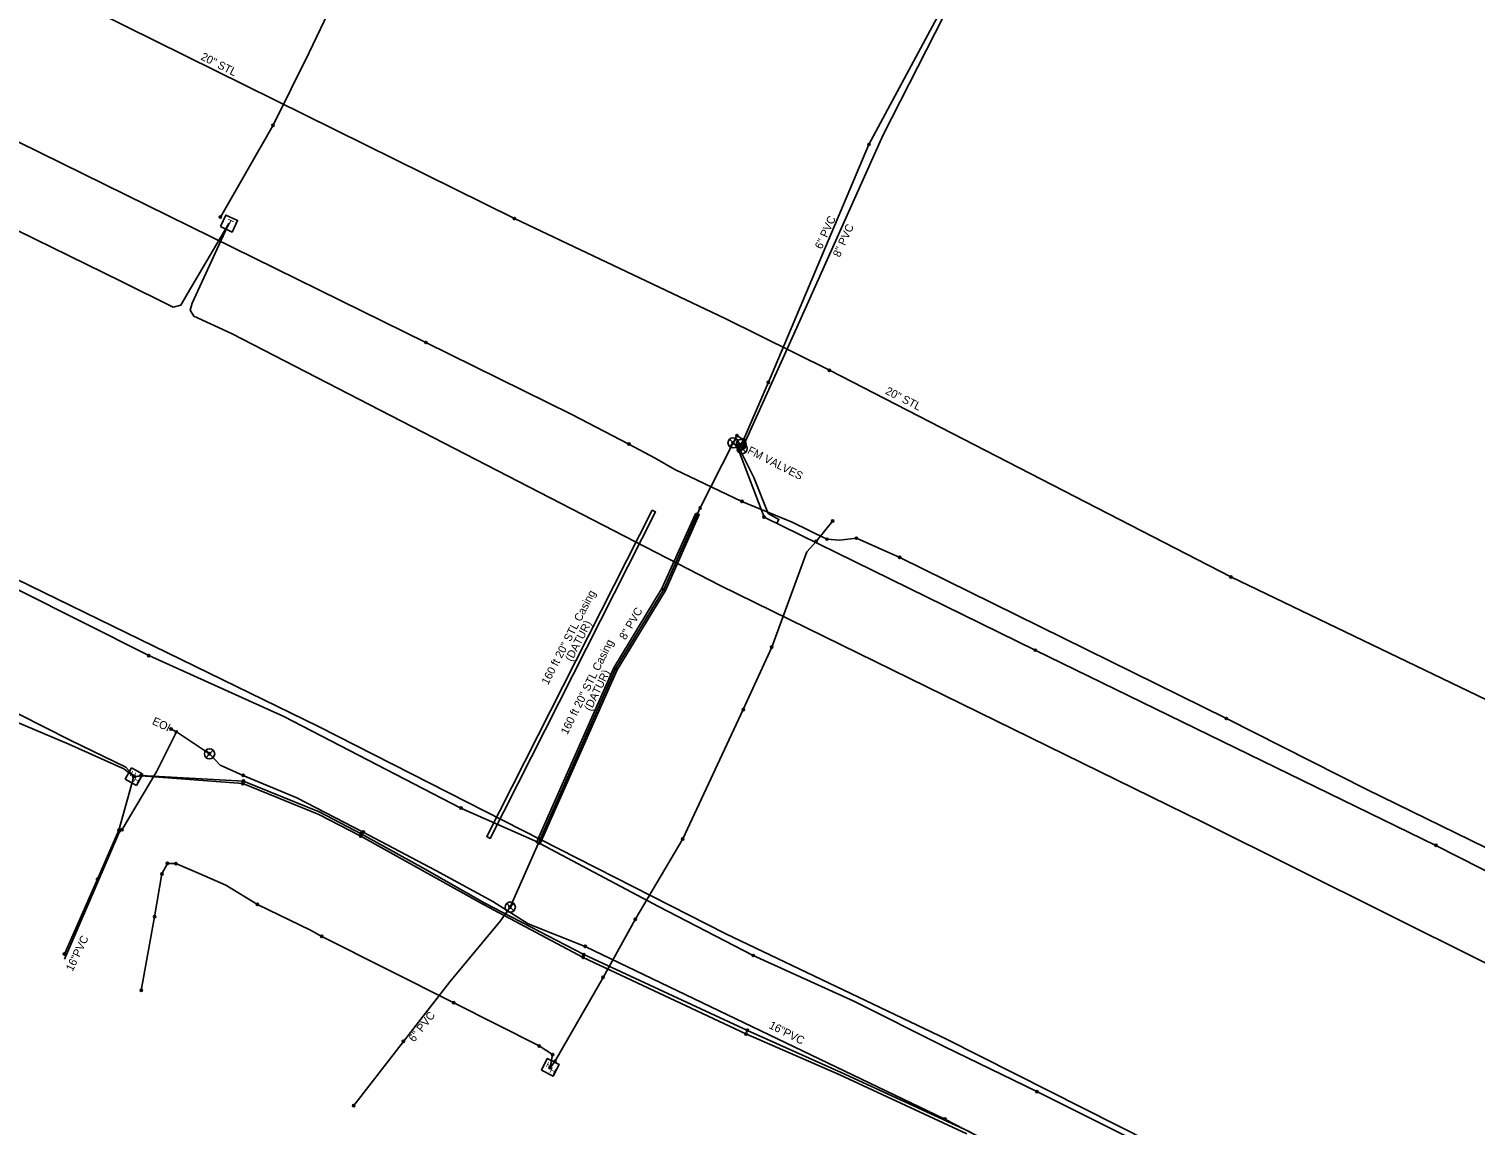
# Model space of a CAD drawing. Extents: x 2244485 to 2250986, y 199568 to 203007.
# Drawn here: x 2245302 to 2245934, y 202136 to 202615 of the extents above; entities that cross this region are included whole.
import ezdxf

# ---------------------------------------------------------------- set-up
doc = ezdxf.new("R2010")
doc.units = 0
for name, color, linetype in [('Default', 7, 'Continuous'), ('Exist Structure Minor Storm Sewer Line Text', 7, 'Continuous'), ('Exist Utilities Gas UG Line SUE LOS B', 7, 'Continuous'), ('Exist Utilities Gas UG Line SUE LOS B Text', 7, 'Continuous'), ('Exist Utilities Power UG Cable SUE LOS B', 7, 'Continuous'), ('Exist Utilities Sanitary Sewer Forced Main SUE LOS B', 7, 'Continuous'), ('Exist Utilities Sanitary Sewer Forced Main SUE LOS B Text', 7, 'Continuous'), ('Exist Utilities Sanitary Sewer Forced Main SUE LOS C', 7, 'Continuous'), ('Exist Utilities Telephone Hand Hole CELL', 7, 'Continuous'), ('Exist Utilities Telephone Pedestal CELL', 7, 'Continuous'), ('Exist Utilities Telephone UG Cable SUE LOS C', 7, 'Continuous'), ('Exist Utilities Telephone UG FO SUE LOS B', 7, 'Continuous'), ('Exist Utilities Telephone UG FO SUE LOS C', 7, 'Continuous'), ('Exist Utilities TV Hand Hole CELL', 7, 'Continuous'), ('Exist Utilities TV UG FO Cable SUE LOS B', 7, 'Continuous'), ('Exist Utilities Water UG Line SUE LOS B', 7, 'Continuous'), ('Exist Utilities Water UG Line SUE LOS B Text', 7, 'Continuous'), ('Exist Utilities Water Valve CELL', 7, 'Continuous')]:
    doc.layers.add(name, color=color, linetype=linetype)

# ---------------------------------------------------------------- blocks, each defined once
blk = doc.blocks.new('SurveyPointCell')
at = {"layer": 'Default'}
for p, q in [((-0.5, 0), (0.5, 0)), ((0, -0.5), (0, 0.5))]:
    blk.add_line(p, q, dxfattribs=at)
blk.add_circle((0, 0), 0.5, dxfattribs=at)

msp = doc.modelspace()

# ---------------------------------------------------------------- linework, layer by layer
at = {"layer": 'Exist Structure Minor Storm Sewer Line Text'}
for points in [[(2245574.64, 202404.29), (2245576.13, 202403.54), (2245503.77, 202260.84), (2245502.28, 202261.59)], [(2245593.72, 202403.05), (2245595.24, 202402.37), (2245580.4, 202369.24), (2245559.29, 202334.56), (2245525.57, 202258.34), (2245524.04, 202259.02), (2245557.81, 202335.34), (2245578.92, 202370.01)]]:
    msp.add_lwpolyline(points, close=True, dxfattribs=at)
at = {"layer": 'Exist Utilities Gas UG Line SUE LOS B'}
msp.add_lwpolyline([(2244658.96, 202958.49), (2244721.96, 202928.3), (2244863.47, 202856.19), (2244912.51, 202831.57), (2245070.07, 202752.33), (2245256.14, 202659.91), (2245331.4, 202622.29), (2245514.38, 202531.76), (2245606.53, 202488.05), (2245652.12, 202465.42), (2245827.69, 202375.08), (2246001.01, 202291.84), (2246162.3, 202211.17), (2246329.12, 202125.74), (2246513.99, 202036.93), (2246642.7, 201974.75), (2246734.96, 201930.33), (2246858.92, 201868.26), (2246999.42, 201799.12), (2247177.53, 201710.71), (2247331.7, 201633.3), (2247466.92, 201567.22), (2247602.4, 201501.88), (2247749.1, 201426.01)], dxfattribs=at)
at = {"layer": 'Exist Utilities Power UG Cable SUE LOS B'}
msp.add_lwpolyline([(2245385.83, 202532.39), (2245408.84, 202572.53), (2245424.65, 202604.36), (2245434.48, 202624.66), (2245451.18, 202657.41), (2245437.28, 202665.96)], dxfattribs=at)
at = {"layer": 'Exist Utilities Sanitary Sewer Forced Main SUE LOS B'}
for points in [[(2245613.42, 202432.81), (2245614.64, 202435.08), (2245625.46, 202460.2), (2245669.41, 202564.11), (2245700.29, 202621.51)], [(2245512.48, 202230.83), (2245558.55, 202334.95), (2245579.66, 202369.62), (2245595.61, 202405.24), (2245610, 202433.72), (2245611.68, 202436.87), (2245614.64, 202435.08)], [(2245613.42, 202432.81), (2245612.33, 202430.62), (2245623.54, 202401.29), (2245742.14, 202343.1), (2245917.37, 202257.79), (2246026.41, 202202.34), (2246210.46, 202111.93), (2246345.24, 202046.28), (2246501.59, 201967.74), (2246585.87, 201926.12), (2246766.44, 201836.2), (2246874.3, 201784.12), (2246993.56, 201724.08), (2247186.6, 201626.85), (2247291.7, 201574.36), (2247419.93, 201509.91), (2247528.38, 201455.85), (2247631.36, 201405.97), (2247735.41, 201350.67), (2247801.59, 201317.51)], [(2245444.17, 202144.04), (2245465.88, 202172.11), (2245486.13, 202198.15), (2245508.27, 202224.8), (2245512.48, 202230.83)]]:
    msp.add_lwpolyline(points, dxfattribs=at)
at = {"layer": 'Exist Utilities Sanitary Sewer Forced Main SUE LOS C'}
msp.add_lwpolyline([(2245629.15, 202398.66), (2245630.09, 202400.26), (2245625.31, 202402.84), (2245619.07, 202418.57), (2245613.43, 202429.99), (2245613.98, 202431.19), (2245637.91, 202484.15), (2245675.61, 202568.28), (2245702.23, 202620.32), (2245700.29, 202621.51)], dxfattribs=at)
at = {"layer": 'Exist Utilities Telephone Hand Hole CELL'}
for p, q in [((2245346.95, 202291.69), (2245344.18, 202286.68)), ((2245351.96, 202288.92), (2245346.95, 202291.69)), ((2245349.19, 202283.91), (2245351.96, 202288.92)), ((2245344.18, 202286.68), (2245349.19, 202283.91)), ((2245348.07, 202287.8), (2245348.07, 202287.8))]:
    msp.add_line(p, q, dxfattribs=at)
at = {"layer": 'Exist Utilities Telephone Pedestal CELL'}
msp.add_line((2245389.55, 202529.63), (2245389.55, 202529.63), dxfattribs=at)
msp.add_lwpolyline([(2245385.88, 202528.23), (2245390.95, 202525.86), (2245393.32, 202530.92), (2245388.26, 202533.3), (2245385.88, 202528.23)], dxfattribs=at)
at = {"layer": 'Exist Utilities Telephone UG Cable SUE LOS C'}
msp.add_lwpolyline([(2245130.24, 202608.24), (2245342.53, 202504.23), (2245365.2, 202493.05), (2245368.49, 202493.82), (2245371.26, 202498.68), (2245389.55, 202529.63), (2245373.43, 202494.83), (2245372.62, 202491.73), (2245374.18, 202489.1), (2245390.76, 202481.45), (2245604.3, 202371.42), (2245815.4, 202267.89), (2246098.91, 202126.77), (2246431.3, 201961.17), (2246435.26, 201960.69), (2246439.92, 201963.48), (2246448.75, 201975.62), (2246463.67, 201997.05), (2246446.22, 201961.62), (2246445.59, 201956.98), (2246446.26, 201954.54), (2246473.42, 201940.75), (2246700.68, 201828.04)], dxfattribs=at)
at = {"layer": 'Exist Utilities Telephone UG FO SUE LOS B'}
for points in [[(2244534.64, 202709.84), (2244609.27, 202669.97), (2244785.74, 202581.01), (2244840.19, 202553.14), (2244956.88, 202500.62), (2244986.55, 202486.03), (2245010.04, 202472.71), (2245040, 202457.4), (2245084.78, 202430.15), (2245170.23, 202380.19), (2245207.23, 202360.21), (2245246.97, 202340.05), (2245286.61, 202320.72), (2245320.18, 202303.77), (2245344.49, 202291.92), (2245347.99, 202287.98)], [(2245260.01, 202583.68), (2245475.72, 202477.57), (2245539.46, 202446.04), (2245564.49, 202433.2), (2245575.96, 202427.09), (2245584.49, 202422.12), (2245613.86, 202408.13), (2245635.9, 202399.1), (2245651.03, 202391.62), (2245656.6, 202391.2), (2245663.92, 202392.06), (2245682.86, 202383.66), (2245825.7, 202313.24), (2245887.18, 202282.16), (2245945.52, 202253.66), (2246007.29, 202222.98), (2246067.19, 202192.91), (2246123.94, 202164.93), (2246186.06, 202132.91)], [(2244991.72, 202447.43), (2244997.62, 202457.3), (2244999.68, 202459.77), (2245003.89, 202458.01), (2245037.21, 202441.81), (2245081.53, 202417.4), (2245166.02, 202372.45), (2245244.84, 202333.87), (2245285.27, 202316.42), (2245319.61, 202302.06), (2245343.58, 202291.26), (2245348.02, 202287.91)], [(2245297.18, 202369.62), (2245354.5, 202340.75), (2245413.57, 202314.06), (2245491.04, 202274.06), (2245523.39, 202259.78), (2245577.45, 202231.04), (2245618.81, 202209.65), (2245662.83, 202189.65), (2245702.29, 202169.93), (2245742.87, 202150.13), (2245837.39, 202103.05), (2245884.95, 202080.1), (2245941.39, 202052.03), (2246102.15, 201972.13), (2246160.8, 201943.07), (2246225.68, 201910.57), (2246354.46, 201846.2), (2246394.94, 201822.07), (2246546.85, 201748.25)], [(2245317.61, 202210.29), (2245332.09, 202242.94), (2245341.42, 202264.38), (2245347.93, 202287.91)], [(2245348.07, 202287.8), (2245351.12, 202288.29), (2245395.88, 202285.86), (2245429.04, 202272.44), (2245447.42, 202262.89), (2245475.01, 202247.57), (2245501.44, 202232.58), (2245544.7, 202210.01), (2245616.26, 202176.91), (2245657.32, 202158.54), (2245712.97, 202132.89), (2245773.8, 202098.67), (2245830.52, 202069.53), (2245875.55, 202047.04), (2245967.13, 202002.37), (2246055.75, 201957.91), (2246176.16, 201896.67), (2246250.38, 201859.8), (2246334.37, 201818.25), (2246368.32, 201799.38), (2246371.55, 201797.86)], [(2245348.07, 202287.8), (2245351.13, 202288.21), (2245395.61, 202284.75), (2245428.9, 202271.31), (2245447.19, 202261.86), (2245500.88, 202231.94), (2245544.46, 202208.81), (2245615.61, 202175.36), (2245656.7, 202157.5), (2245712.28, 202131.67)]]:
    msp.add_lwpolyline(points, dxfattribs=at)
at = {"layer": 'Exist Utilities Telephone UG FO SUE LOS C'}
msp.add_lwpolyline([(2244555.09, 202740.38), (2244612.45, 202712.07), (2244680.5, 202678.83), (2244750.01, 202644.92), (2244809.78, 202614.66), (2244896.14, 202572.42), (2244969.14, 202536), (2245027.26, 202506.94), (2245218.26, 202412.25), (2245428.66, 202309.78), (2245606.8, 202219.11), (2245703.35, 202173.01), (2245852.59, 202097.7), (2245983.22, 202033.13), (2246107.4, 201971.58), (2246219.73, 201915.39), (2246355.16, 201847.48), (2246395.74, 201823.66), (2246448.95, 201797.92), (2246548.24, 201751.03)], dxfattribs=at)
at = {"layer": 'Exist Utilities TV Hand Hole CELL'}
msp.add_line((2245530.06, 202160.76), (2245530.06, 202160.76), dxfattribs=at)
msp.add_lwpolyline([(2245526.21, 202159.46), (2245531.36, 202156.91), (2245533.91, 202162.06), (2245528.76, 202164.61), (2245526.21, 202159.46)], dxfattribs=at)
at = {"layer": 'Exist Utilities TV UG FO Cable SUE LOS B'}
msp.add_lwpolyline([(2245351.21, 202194.41), (2245357.04, 202226.58), (2245360.28, 202245.31), (2245362.68, 202249.91), (2245366.35, 202249.79), (2245376.5, 202245.43), (2245388.24, 202240.37), (2245402.01, 202231.99), (2245425.26, 202220.72), (2245430.16, 202217.96), (2245487.84, 202189), (2245525.23, 202170.15), (2245531.08, 202166.34), (2245530.01, 202160.61), (2245532.12, 202163.34), (2245553.14, 202200.08), (2245567.26, 202225.44), (2245588, 202260.58), (2245614.46, 202317.14), (2245626.91, 202344.47), (2245642.21, 202386.12), (2245646.33, 202390.64), (2245653.56, 202399.57)], dxfattribs=at)
at = {"layer": 'Exist Utilities Water UG Line SUE LOS B'}
for points in [[(2245317.6, 202208.11), (2245341.46, 202263.05), (2245342.85, 202264.7), (2245357.99, 202290.22), (2245366.59, 202307.41)], [(2245364.27, 202308.61), (2245366.59, 202307.41), (2245381, 202297.8), (2245385.67, 202292.83), (2245395.79, 202288.35), (2245419.32, 202278.5), (2245448.28, 202263.59), (2245479.99, 202246.8), (2245504.9, 202233.28), (2245520.47, 202223.52), (2245545.35, 202213.61), (2245702.65, 202138.15), (2245808.82, 202083.18), (2245963.17, 202009.49), (2246100.08, 201939.27), (2246176.18, 201901.25), (2246305.63, 201836.71), (2246381.12, 201802.25)]]:
    msp.add_lwpolyline(points, dxfattribs=at)
at = {"layer": 'Exist Utilities Water Valve CELL'}
for points in [[(2245611.58, 202435.29), (2245608.43, 202432.15), (2245610.01, 202433.72), (2245611.58, 202432.15), (2245608.43, 202435.29)], [(2245615.11, 202434.58), (2245611.96, 202431.43), (2245613.53, 202433.01), (2245615.11, 202431.43), (2245611.96, 202434.58)], [(2245615.55, 202432.76), (2245612.4, 202429.61), (2245613.98, 202431.19), (2245615.55, 202429.61), (2245612.4, 202432.76)], [(2245382.69, 202299.36), (2245379.54, 202296.21), (2245381.11, 202297.79), (2245382.69, 202296.21), (2245379.54, 202299.36)], [(2245514.17, 202232.38), (2245511.02, 202229.23), (2245512.59, 202230.81), (2245514.17, 202229.23), (2245511.02, 202232.38)]]:
    msp.add_lwpolyline(points, dxfattribs=at)
for centre in [(2245610.01, 202433.72), (2245613.53, 202433.01), (2245613.98, 202431.19), (2245381.11, 202297.79), (2245512.59, 202230.81)]:
    msp.add_circle(centre, 2.23, dxfattribs=at)

# ---------------------------------------------------------------- block references
at = {"layer": 'Default'}
for p in [(2245408.84, 202572.53), (2245669.41, 202564.11), (2245385.83, 202532.39), (2245514.38, 202531.76), (2245475.72, 202477.57), (2245652.12, 202465.42), (2245625.46, 202460.2), (2245610, 202433.72), (2245611.68, 202436.87), (2245614.64, 202435.08), (2245614.64, 202435.08), (2245564.49, 202433.2), (2245612.33, 202430.62), (2245613.42, 202432.81), (2245613.42, 202432.81), (2245613.98, 202431.19), (2245613.86, 202408.13), (2245595.61, 202405.24), (2245623.54, 202401.29), (2245653.56, 202399.57), (2245646.33, 202390.64), (2245651.03, 202391.62), (2245663.92, 202392.06), (2245682.86, 202383.66), (2245827.69, 202375.08), (2245579.66, 202369.62), (2245354.5, 202340.75), (2245626.91, 202344.47), (2245742.14, 202343.1), (2245558.55, 202334.95), (2245614.46, 202317.14), (2245825.7, 202313.24), (2245364.27, 202308.61), (2245366.59, 202307.41), (2245366.59, 202307.41), (2245381, 202297.8), (2245347.93, 202287.91), (2245347.99, 202287.98), (2245348.02, 202287.91), (2245351.12, 202288.29), (2245351.13, 202288.21), (2245395.79, 202288.35), (2245395.61, 202284.75), (2245395.88, 202285.86), (2245491.04, 202274.06), (2245341.42, 202264.38), (2245342.85, 202264.7), (2245447.42, 202262.89), (2245448.28, 202263.59), (2245447.19, 202261.86), (2245588, 202260.58), (2245917.37, 202257.79), (2245362.68, 202249.91), (2245360.28, 202245.31), (2245366.35, 202249.79), (2245332.09, 202242.94), (2245402.01, 202231.99), (2245357.04, 202226.58), (2245512.48, 202230.83), (2245567.26, 202225.44), (2245430.16, 202217.96), (2245545.35, 202213.61), (2245317.61, 202210.29), (2245544.46, 202208.81), (2245544.7, 202210.01), (2245618.81, 202209.65), (2245553.14, 202200.08), (2245351.21, 202194.41), (2245487.84, 202189), (2245615.61, 202175.36), (2245616.26, 202176.91), (2245465.88, 202172.11), (2245525.23, 202170.15), (2245531.08, 202166.34), (2245532.12, 202163.34), (2245530.01, 202160.61), (2245742.87, 202150.13), (2245444.17, 202144.04), (2245702.65, 202138.15)]:
    msp.add_blockref('SurveyPointCell', p, dxfattribs=at)

# ---------------------------------------------------------------- texts
at = {"layer": 'Exist Structure Minor Storm Sewer Line Text'}
for s, rotation, p in [('160 ft 20" STL Casing', 62.68084, (2245529.1, 202327.68)), ('(DATUR)', 62.68084, (2245539.47, 202337.85)), ('160 ft 20" STL Casing', 63.57258, (2245537.57, 202305.89)), ('(DATUR)', 63.57258, (2245547.79, 202316.22))]:
    msp.add_text(s, height=3.5, rotation=rotation, dxfattribs=at).set_placement(p)
at = {"layer": 'Exist Utilities Gas UG Line SUE LOS B Text'}
for p in [(2245376.96, 202601.42), (2245676.26, 202455.29)]:
    msp.add_text('20" STL', height=3.5, rotation=333.09153, dxfattribs=at).set_placement(p)
at = {"layer": 'Exist Utilities Sanitary Sewer Forced Main SUE LOS B'}
msp.add_text('FM VALVES', height=3.5, rotation=333.09153, dxfattribs=at).set_placement((2245616, 202429.28))
at = {"layer": 'Exist Utilities Sanitary Sewer Forced Main SUE LOS B Text'}
for s, rotation, p in [('6" PVC', 65.60363, (2245648.75, 202518.08)), ('8" PVC', 65.43585, (2245656.63, 202514.57)), ('8" PVC ', 60.17152, (2245563, 202347.29)), ('6" PVC', 51.68752, (2245470.53, 202171.54))]:
    msp.add_text(s, height=3.5, rotation=rotation, dxfattribs=at).set_placement(p)
at = {"layer": 'Exist Utilities Telephone Hand Hole CELL'}
for p in [(2245345.96, 202288.29), (2245347.5, 202285.76)]:
    msp.add_text('H', height=2.5, rotation=331.07712, dxfattribs=at).set_placement(p)
at = {"layer": 'Exist Utilities Telephone Pedestal CELL'}
msp.add_text('T', height=3.42, rotation=334.87134, dxfattribs=at).set_placement((2245387.8, 202528.56))
at = {"layer": 'Exist Utilities TV Hand Hole CELL'}
for p in [(2245527.9, 202161.1), (2245529.56, 202158.65)]:
    msp.add_text('H', height=2.5, rotation=333.68902, dxfattribs=at).set_placement(p)
at = {"layer": 'Exist Utilities Water UG Line SUE LOS B'}
msp.add_text('EOI', height=3.5, rotation=334.3343, dxfattribs=at).set_placement((2245355.68, 202310.91))
at = {"layer": 'Exist Utilities Water UG Line SUE LOS B Text'}
for rotation, p in [(64.37325, (2245321.19, 202202.45)), (333.09153, (2245625.4, 202178.06))]:
    msp.add_text('16"PVC', height=3.5, rotation=rotation, dxfattribs=at).set_placement(p)

doc.saveas('drawing.dxf')
